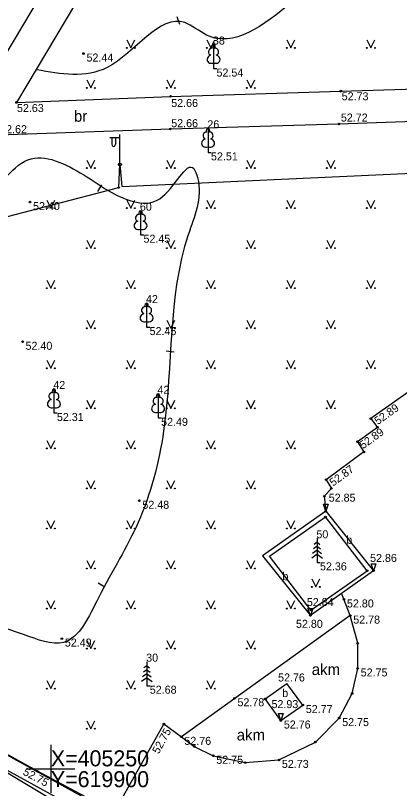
# Model space of a CAD drawing. Extents: x 619806 to 620082, y 405176 to 405386.
# Drawn here: x 619897.79 to 619921.79, y 405248.76 to 405297.03 of the extents above; entities that cross this region are included whole.
import ezdxf

# ---------------------------------------------------------------- set-up
doc = ezdxf.new("R2010")
doc.units = 0
for name, color, linetype in [('APGS_ELEM_####_####_#', 7, 'Continuous'), ('APGS_VADP_ZSPR_####_#', 7, 'Continuous'), ('BUVE_BDET_####_####_#', 7, 'Continuous'), ('BUVE_BDET_####_TKST_#', 7, 'Continuous'), ('CELI_CMAL_####_####_#', 7, 'Continuous'), ('CELI_CSEG_####_TKST_#', 7, 'Continuous'), ('CELI_SEGL_####_####_#', 7, 'Continuous'), ('GEOD_ELEM_####_####_#', 7, 'Continuous'), ('GEOD_KORD_####_TKST_#', 7, 'Continuous'), ('RELJ_AATZ_####_TKST_#', 7, 'Continuous'), ('RELJ_ELEM_####_####_#', 7, 'Continuous'), ('RELJ_HORZ_PAMT_####_#', 7, 'Continuous'), ('ROBZ_UZMR_####_####_#', 7, 'Continuous'), ('SAKK_KKAN_####_####_#', 7, 'Continuous'), ('TERT_DIAM_####_TKST_#', 7, 'Continuous'), ('TERT_ELEM_####_####_#', 7, 'Continuous')]:
    doc.layers.add(name, color=color, linetype=linetype)

msp = doc.modelspace()

# ---------------------------------------------------------------- linework, layer by layer
at = {"layer": 'APGS_ELEM_####_####_#'}
for p, q in [((619904.319, 405289.388), (619903.684, 405289.383)), ((619903.819, 405289.384), (619903.819, 405288.992)), ((619904.029, 405289.386), (619904.029, 405288.992)), ((619904.319, 405287.722), (619904.319, 405289.604))]:
    msp.add_line(p, q, dxfattribs=at)
msp.add_circle((619904.319, 405287.722), 0.09, dxfattribs=at)
msp.add_ellipse((619903.924, 405288.992), major_axis=(0, 0.151), ratio=0.695971, start_param=1.570796, end_param=4.712389, dxfattribs=at)
at = {"layer": 'APGS_VADP_ZSPR_####_#'}
msp.add_lwpolyline([(619889.151, 405287.633), (619889.486, 405287.011), (619889.44, 405286.121), (619891.102, 405284.875), (619895.261, 405283.948), (619904.24, 405286.286), (619904.319, 405287.722), (619904.441, 405286.35), (619922.582, 405287.176), (619922.83, 405287.786), (619922.954, 405287.209), (619932.902, 405287.177), (619938.46, 405286.492), (619942.211, 405287.557), (619942.781, 405287.929)], dxfattribs=at)
at = {"layer": 'BUVE_BDET_####_####_#'}
for p, q in [((619917.174, 405266.076), (619913.225, 405263.285)), ((619917.174, 405266.076), (619920.16, 405262.362)), ((619913.654, 405263.264), (619917.162, 405265.722)), ((619919.758, 405262.363), (619917.162, 405265.722)), ((619913.225, 405263.285), (619916.211, 405259.571)), ((619916.25, 405259.905), (619913.654, 405263.264)), ((619920.16, 405262.362), (619916.211, 405259.571)), ((619916.25, 405259.905), (619919.758, 405262.363)), ((619913.379, 405254.36), (619914.751, 405255.325)), ((619915.741, 405253.976), (619914.751, 405255.325)), ((619914.369, 405253.011), (619913.379, 405254.36)), ((619914.369, 405253.011), (619915.741, 405253.976))]:
    msp.add_line(p, q, dxfattribs=at)
at = {"layer": 'CELI_CMAL_####_####_#'}
msp.add_line((619918.708, 405259.562), (619908.156, 405251.991), dxfattribs=at)
for points in [[(619931.221, 405348.79), (619927.084, 405342.173), (619917.705, 405328.076), (619912.167, 405319.566), (619908.262, 405313.163), (619901.141, 405301.297), (619895.285, 405291.495)], [(619923.8, 405331.651), (619922.909, 405332.209), (619919.472, 405326.95), (619913.839, 405318.4), (619910.247, 405312.462), (619903.419, 405300.947), (619897.856, 405291.596), (619907.48, 405291.973), (619918.115, 405292.304), (619928.883, 405292.628), (619940.313, 405293.006), (619951.468, 405293.381)], [(619896.721, 405289.572), (619907.468, 405289.939), (619918, 405290.255), (619929.205, 405290.656), (619939.879, 405290.972), (619948.401, 405291.292), (619944.499, 405288.598), (619934.453, 405281.815), (619926.054, 405276.128), (619919.99, 405271.86), (619920.405, 405271.311), (619919.157, 405270.417), (619919.559, 405269.777), (619917.19, 405268.043), (619917.528, 405267.503), (619917.083, 405267.011)], [(619917.083, 405267.011), (619917.174, 405266.076)], [(619918.708, 405259.562), (619918.164, 405260.952)], [(619907.059, 405252.795), (619903.949, 405247.281), (619899.158, 405249.84), (619889.566, 405255.126)], [(619907.059, 405252.795), (619908.156, 405251.991)]]:
    msp.add_lwpolyline(points, dxfattribs=at)
at = {"layer": 'CELI_SEGL_####_####_#'}
msp.add_lwpolyline([(619908.156, 405251.991), (619908.96, 405251.391), (619910.15, 405250.809), (619912.149, 405250.384), (619914.248, 405250.551), (619916.525, 405251.669), (619918.015, 405253.162), (619918.824, 405254.696), (619919.172, 405256.263), (619919.174, 405257.833), (619918.708, 405259.562)], dxfattribs=at)
at = {"layer": 'GEOD_ELEM_####_####_#'}
for p, q in [((619900, 405251.5), (619900, 405250)), ((619898.5, 405250), (619900, 405250)), ((619900, 405250), (619900, 405248.5)), ((619900, 405250), (619901.5, 405250))]:
    msp.add_line(p, q, dxfattribs=at)
at = {"layer": 'RELJ_ELEM_####_####_#'}
for points in [[(619917.024, 405266.509), (619917.324, 405266.509), (619917.174, 405266.076)], [(619920.01, 405262.795), (619920.31, 405262.795), (619920.16, 405262.362)], [(619916.061, 405260.004), (619916.361, 405260.004), (619916.211, 405259.571)], [(619914.219, 405253.444), (619914.519, 405253.444), (619914.369, 405253.011)]]:
    msp.add_lwpolyline(points, close=True, dxfattribs=at)
for centre in [(619902.042, 405294.649), (619918.115, 405292.304), (619897.856, 405291.596), (619907.48, 405291.973), (619918, 405290.255), (619907.468, 405289.939), (619904.24, 405286.286), (619898.701, 405285.374), (619898.232, 405276.657), (619919.99, 405271.86), (619920.405, 405271.311), (619919.157, 405270.417), (619919.559, 405269.777), (619917.19, 405268.043), (619917.528, 405267.503), (619917.083, 405267.011), (619905.532, 405266.73), (619917.174, 405266.076), (619917.162, 405265.722), (619919.758, 405262.363), (619920.16, 405262.362), (619918.314, 405260.569), (619916.25, 405259.905), (619916.211, 405259.571), (619918.708, 405259.562), (619900.688, 405258.126), (619919.174, 405257.833), (619919.172, 405256.263), (619911.473, 405254.4), (619913.379, 405254.36), (619913.414, 405254.36), (619918.824, 405254.696), (619915.741, 405253.976), (619914.369, 405253.011), (619918.015, 405253.162), (619907.059, 405252.795), (619908.156, 405251.991), (619916.525, 405251.669), (619908.96, 405251.391), (619910.15, 405250.809), (619914.248, 405250.551), (619912.149, 405250.384), (619899.158, 405249.84)]:
    msp.add_circle(centre, 0.05, dxfattribs=at)
at = {"layer": 'RELJ_HORZ_PAMT_####_#'}
for p, q in [((619907.874, 405296.963), (619908.041, 405296.492)), ((619902.928, 405286.035), (619903.188, 405286.462)), ((619907.198, 405276.089), (619907.695, 405276.03)), ((619902.951, 405261.609), (619903.381, 405261.354))]:
    msp.add_line(p, q, dxfattribs=at)
for points in [[(619907.956, 405308.464), (619910.402, 405307.562), (619913.86, 405304.951), (619915.602, 405304.09), (619915.602, 405305.597), (619912.968, 405313.592), (619912.89, 405315.511), (619914.687, 405318.349), (619915.7, 405320.324), (619916.9, 405321.328), (619919.524, 405322.347), (619920.794, 405321.7), (619918.865, 405319.529), (619916.618, 405315.954), (619917.647, 405309.917), (619920.445, 405301.831), (619920.93, 405298.602), (619919.742, 405298.823), (619918.41, 405299.521), (619915.057, 405297.864), (619909.729, 405295.803), (619908.377, 405296.58), (619903.524, 405293.78), (619899.119, 405293.642)], [(619887.855, 405269.148), (619889.12, 405269.976), (619890.345, 405272.168), (619891.345, 405274.665), (619892.785, 405275.65), (619894.673, 405276.824), (619895.637, 405278.889), (619895.637, 405282.116), (619896.178, 405285.879), (619897.087, 405286.842), (619898.566, 405288.02), (619902.05, 405287.072), (619905.151, 405285.41), (619906.813, 405285.589), (619908.935, 405287.464), (619909.163, 405286.902), (619908.582, 405283.331), (619907.046, 405271.1), (619905.455, 405265.372), (619902.979, 405260.677), (619900.798, 405257.889), (619898.289, 405258.38), (619891.711, 405260.242), (619887.92, 405262.299), (619887.202, 405264.358), (619886.645, 405266.658)]]:
    msp.add_spline(points, degree=3, dxfattribs=at)
at = {"layer": 'ROBZ_UZMR_####_####_#'}
msp.add_line((619903.919, 405247.191), (619882.718, 405258.864), dxfattribs=at)
at = {"layer": 'SAKK_KKAN_####_####_#'}
for points in [[(619816.151, 405294.73), (619816.825, 405294), (619832.922, 405285.576), (619895.115, 405251.073), (619918.714, 405238.138)], [(619895.171, 405251.006), (619903.851, 405245.802), (619901.291, 405240.588)]]:
    msp.add_lwpolyline(points, dxfattribs=at)
at = {"layer": 'TERT_ELEM_####_####_#'}
for p, q in [((619904.75, 405295.5), (619905, 405295)), ((619905, 405295), (619905.25, 405295.5)), ((619909.75, 405295.5), (619910, 405295)), ((619910, 405295), (619910.25, 405295.5)), ((619914.75, 405295.5), (619915, 405295)), ((619915, 405295), (619915.25, 405295.5)), ((619919.75, 405295.5), (619920, 405295)), ((619920, 405295), (619920.25, 405295.5)), ((619910.164, 405294.058), (619910.164, 405293.711)), ((619910.164, 405293.711), (619910.364, 405293.711)), ((619902.25, 405293), (619902.5, 405292.5)), ((619902.5, 405292.5), (619902.75, 405293)), ((619907.25, 405293), (619907.5, 405292.5)), ((619907.5, 405292.5), (619907.75, 405293)), ((619912.25, 405293), (619912.5, 405292.5)), ((619912.5, 405292.5), (619912.75, 405293)), ((619909.818, 405288.827), (619909.818, 405288.48)), ((619909.818, 405288.48), (619910.018, 405288.48)), ((619902.25, 405288), (619902.5, 405287.5)), ((619902.5, 405287.5), (619902.75, 405288)), ((619907.25, 405288), (619907.5, 405287.5)), ((619907.5, 405287.5), (619907.75, 405288)), ((619912.25, 405288), (619912.5, 405287.5)), ((619912.5, 405287.5), (619912.75, 405288)), ((619917.25, 405288), (619917.5, 405287.5)), ((619917.5, 405287.5), (619917.75, 405288)), ((619899.75, 405285.5), (619900, 405285)), ((619900, 405285), (619900.25, 405285.5)), ((619904.75, 405285.5), (619905, 405285)), ((619905, 405285), (619905.25, 405285.5)), ((619909.75, 405285.5), (619910, 405285)), ((619910, 405285), (619910.25, 405285.5)), ((619914.75, 405285.5), (619915, 405285)), ((619915, 405285), (619915.25, 405285.5)), ((619919.75, 405285.5), (619920, 405285)), ((619920, 405285), (619920.25, 405285.5)), ((619905.601, 405283.686), (619905.601, 405283.339)), ((619902.25, 405283), (619902.5, 405282.5)), ((619902.5, 405282.5), (619902.75, 405283)), ((619905.601, 405283.339), (619905.801, 405283.339)), ((619907.25, 405283), (619907.5, 405282.5)), ((619907.5, 405282.5), (619907.75, 405283)), ((619912.25, 405283), (619912.5, 405282.5)), ((619912.5, 405282.5), (619912.75, 405283)), ((619917.25, 405283), (619917.5, 405282.5)), ((619917.5, 405282.5), (619917.75, 405283)), ((619899.75, 405280.5), (619900, 405280)), ((619900, 405280), (619900.25, 405280.5)), ((619904.75, 405280.5), (619905, 405280)), ((619905, 405280), (619905.25, 405280.5)), ((619909.75, 405280.5), (619910, 405280)), ((619910, 405280), (619910.25, 405280.5)), ((619914.75, 405280.5), (619915, 405280)), ((619915, 405280), (619915.25, 405280.5)), ((619919.75, 405280.5), (619920, 405280)), ((619920, 405280), (619920.25, 405280.5)), ((619902.25, 405278), (619902.5, 405277.5)), ((619902.5, 405277.5), (619902.75, 405278)), ((619905.983, 405277.92), (619905.983, 405277.573)), ((619905.983, 405277.573), (619906.183, 405277.573)), ((619907.25, 405278), (619907.5, 405277.5)), ((619907.5, 405277.5), (619907.75, 405278)), ((619912.25, 405278), (619912.5, 405277.5)), ((619912.5, 405277.5), (619912.75, 405278)), ((619917.25, 405278), (619917.5, 405277.5)), ((619917.5, 405277.5), (619917.75, 405278)), ((619899.75, 405275.5), (619900, 405275)), ((619900, 405275), (619900.25, 405275.5)), ((619904.75, 405275.5), (619905, 405275)), ((619905, 405275), (619905.25, 405275.5)), ((619909.75, 405275.5), (619910, 405275)), ((619910, 405275), (619910.25, 405275.5)), ((619914.75, 405275.5), (619915, 405275)), ((619915, 405275), (619915.25, 405275.5)), ((619919.75, 405275.5), (619920, 405275)), ((619920, 405275), (619920.25, 405275.5)), ((619902.25, 405273), (619902.5, 405272.5)), ((619902.5, 405272.5), (619902.75, 405273)), ((619907.25, 405273), (619907.5, 405272.5)), ((619907.5, 405272.5), (619907.75, 405273)), ((619912.25, 405273), (619912.5, 405272.5)), ((619912.5, 405272.5), (619912.75, 405273)), ((619917.25, 405273), (619917.5, 405272.5)), ((619917.5, 405272.5), (619917.75, 405273)), ((619900.191, 405272.556), (619900.191, 405272.209)), ((619906.702, 405272.255), (619906.702, 405271.908)), ((619900.191, 405272.209), (619900.391, 405272.209)), ((619906.702, 405271.908), (619906.902, 405271.908)), ((619899.75, 405270.5), (619900, 405270)), ((619900, 405270), (619900.25, 405270.5)), ((619904.75, 405270.5), (619905, 405270)), ((619905, 405270), (619905.25, 405270.5)), ((619909.75, 405270.5), (619910, 405270)), ((619910, 405270), (619910.25, 405270.5)), ((619914.75, 405270.5), (619915, 405270)), ((619915, 405270), (619915.25, 405270.5)), ((619902.25, 405268), (619902.5, 405267.5)), ((619902.5, 405267.5), (619902.75, 405268)), ((619907.25, 405268), (619907.5, 405267.5)), ((619907.5, 405267.5), (619907.75, 405268)), ((619912.25, 405268), (619912.5, 405267.5)), ((619912.5, 405267.5), (619912.75, 405268)), ((619899.75, 405265.5), (619900, 405265)), ((619900, 405265), (619900.25, 405265.5)), ((619904.75, 405265.5), (619905, 405265)), ((619905, 405265), (619905.25, 405265.5)), ((619909.75, 405265.5), (619910, 405265)), ((619910, 405265), (619910.25, 405265.5)), ((619914.75, 405265.5), (619915, 405265)), ((619915, 405265), (619915.25, 405265.5)), ((619916.629, 405264.136), (619916.453, 405264.008)), ((619916.629, 405264.386), (619916.629, 405262.886)), ((619916.629, 405264.136), (619916.803, 405264.008)), ((619916.629, 405263.636), (619916.351, 405263.432)), ((619916.629, 405263.886), (619916.413, 405263.728)), ((619916.629, 405263.886), (619916.845, 405263.728)), ((619916.629, 405263.636), (619916.907, 405263.432)), ((619916.629, 405263.386), (619916.297, 405263.142)), ((619916.629, 405263.386), (619916.963, 405263.142)), ((619902.25, 405263), (619902.5, 405262.5)), ((619902.5, 405262.5), (619902.75, 405263)), ((619907.25, 405263), (619907.5, 405262.5)), ((619907.5, 405262.5), (619907.75, 405263)), ((619912.25, 405263), (619912.5, 405262.5)), ((619912.5, 405262.5), (619912.75, 405263)), ((619916.629, 405262.886), (619916.829, 405262.886)), ((619916.298, 405261.851), (619916.548, 405261.351)), ((619916.548, 405261.351), (619916.798, 405261.851)), ((619899.75, 405260.5), (619900, 405260)), ((619900, 405260), (619900.25, 405260.5)), ((619904.75, 405260.5), (619905, 405260)), ((619905, 405260), (619905.25, 405260.5)), ((619909.75, 405260.5), (619910, 405260)), ((619910, 405260), (619910.25, 405260.5)), ((619914.75, 405260.5), (619915, 405260)), ((619915, 405260), (619915.25, 405260.5)), ((619902.25, 405258), (619902.5, 405257.5)), ((619902.5, 405257.5), (619902.75, 405258)), ((619907.25, 405258), (619907.5, 405257.5)), ((619907.5, 405257.5), (619907.75, 405258)), ((619912.25, 405258), (619912.5, 405257.5)), ((619912.5, 405257.5), (619912.75, 405258)), ((619905.994, 405256.434), (619905.818, 405256.306)), ((619905.994, 405256.684), (619905.994, 405255.184)), ((619905.994, 405256.434), (619906.168, 405256.306)), ((619905.994, 405255.934), (619905.716, 405255.73)), ((619905.994, 405256.184), (619905.778, 405256.026)), ((619905.994, 405256.184), (619906.21, 405256.026)), ((619905.994, 405255.934), (619906.272, 405255.73)), ((619899.75, 405255.5), (619900, 405255)), ((619900, 405255), (619900.25, 405255.5)), ((619904.75, 405255.5), (619905, 405255)), ((619905, 405255), (619905.25, 405255.5)), ((619905.994, 405255.684), (619905.662, 405255.44)), ((619905.994, 405255.684), (619906.328, 405255.44)), ((619909.75, 405255.5), (619910, 405255)), ((619910, 405255), (619910.25, 405255.5)), ((619905.994, 405255.184), (619906.194, 405255.184)), ((619902.25, 405253), (619902.5, 405252.5)), ((619902.5, 405252.5), (619902.75, 405253))]:
    msp.add_line(p, q, dxfattribs=at)
for points in [[(619910.164, 405295.211), (619910.164, 405294.058)], [(619910.254, 405294.979), (619910.253, 405294.98)], [(619909.818, 405289.98), (619909.818, 405288.827)], [(619909.908, 405289.748), (619909.907, 405289.749)], [(619905.601, 405284.839), (619905.601, 405283.686)], [(619905.691, 405284.607), (619905.69, 405284.608)], [(619905.983, 405279.073), (619905.983, 405277.92)], [(619906.073, 405278.841), (619906.072, 405278.842)], [(619900.191, 405273.709), (619900.191, 405272.556)], [(619900.281, 405273.477), (619900.28, 405273.478)], [(619906.702, 405273.408), (619906.702, 405272.255)], [(619906.792, 405273.176), (619906.791, 405273.177)]]:
    msp.add_lwpolyline(points, dxfattribs=at)
for centre, radius in [((619904.75, 405295), 0.028), ((619905.25, 405295), 0.0263), ((619909.75, 405295), 0.028), ((619910.25, 405295), 0.0263), ((619914.75, 405295), 0.028), ((619915.25, 405295), 0.0263), ((619919.75, 405295), 0.028), ((619920.25, 405295), 0.0263), ((619902.25, 405292.5), 0.028), ((619902.75, 405292.5), 0.0263), ((619907.25, 405292.5), 0.028), ((619907.75, 405292.5), 0.0263), ((619912.25, 405292.5), 0.028), ((619912.75, 405292.5), 0.0263), ((619902.25, 405287.5), 0.028), ((619902.75, 405287.5), 0.0263), ((619907.25, 405287.5), 0.028), ((619907.75, 405287.5), 0.0263), ((619912.25, 405287.5), 0.028), ((619912.75, 405287.5), 0.0263), ((619917.25, 405287.5), 0.028), ((619917.75, 405287.5), 0.0263), ((619899.75, 405285), 0.028), ((619900.25, 405285), 0.0263), ((619904.75, 405285), 0.028), ((619905.25, 405285), 0.0263), ((619909.75, 405285), 0.028), ((619910.25, 405285), 0.0263), ((619914.75, 405285), 0.028), ((619915.25, 405285), 0.0263), ((619919.75, 405285), 0.028), ((619920.25, 405285), 0.0263), ((619902.25, 405282.5), 0.028), ((619902.75, 405282.5), 0.0263), ((619907.25, 405282.5), 0.028), ((619907.75, 405282.5), 0.0263), ((619912.25, 405282.5), 0.028), ((619912.75, 405282.5), 0.0263), ((619917.25, 405282.5), 0.028), ((619917.75, 405282.5), 0.0263), ((619899.75, 405280), 0.028), ((619900.25, 405280), 0.0263), ((619904.75, 405280), 0.028), ((619905.25, 405280), 0.0263), ((619909.75, 405280), 0.028), ((619910.25, 405280), 0.0263), ((619914.75, 405280), 0.028), ((619915.25, 405280), 0.0263), ((619919.75, 405280), 0.028), ((619920.25, 405280), 0.0263), ((619902.25, 405277.5), 0.028), ((619902.75, 405277.5), 0.0263), ((619907.25, 405277.5), 0.028), ((619907.75, 405277.5), 0.0263), ((619912.25, 405277.5), 0.028), ((619912.75, 405277.5), 0.0263), ((619917.25, 405277.5), 0.028), ((619917.75, 405277.5), 0.0263), ((619899.75, 405275), 0.028), ((619900.25, 405275), 0.0263), ((619904.75, 405275), 0.028), ((619905.25, 405275), 0.0263), ((619909.75, 405275), 0.028), ((619910.25, 405275), 0.0263), ((619914.75, 405275), 0.028), ((619915.25, 405275), 0.0263), ((619919.75, 405275), 0.028), ((619920.25, 405275), 0.0263), ((619902.25, 405272.5), 0.028), ((619902.75, 405272.5), 0.0263), ((619907.25, 405272.5), 0.028), ((619907.75, 405272.5), 0.0263), ((619912.25, 405272.5), 0.028), ((619912.75, 405272.5), 0.0263), ((619917.25, 405272.5), 0.028), ((619917.75, 405272.5), 0.0263), ((619899.75, 405270), 0.028), ((619900.25, 405270), 0.0263), ((619904.75, 405270), 0.028), ((619905.25, 405270), 0.0263), ((619909.75, 405270), 0.028), ((619910.25, 405270), 0.0263), ((619914.75, 405270), 0.028), ((619915.25, 405270), 0.0263), ((619902.25, 405267.5), 0.028), ((619902.75, 405267.5), 0.0263), ((619907.25, 405267.5), 0.028), ((619907.75, 405267.5), 0.0263), ((619912.25, 405267.5), 0.028), ((619912.75, 405267.5), 0.0263), ((619899.75, 405265), 0.028), ((619900.25, 405265), 0.0263), ((619904.75, 405265), 0.028), ((619905.25, 405265), 0.0263), ((619909.75, 405265), 0.028), ((619910.25, 405265), 0.0263), ((619914.75, 405265), 0.028), ((619915.25, 405265), 0.0263), ((619902.25, 405262.5), 0.028), ((619902.75, 405262.5), 0.0263), ((619907.25, 405262.5), 0.028), ((619907.75, 405262.5), 0.0263), ((619912.25, 405262.5), 0.028), ((619912.75, 405262.5), 0.0263), ((619916.298, 405261.35), 0.028), ((619916.798, 405261.35), 0.0263), ((619899.75, 405260), 0.028), ((619900.25, 405260), 0.0263), ((619904.75, 405260), 0.028), ((619905.25, 405260), 0.0263), ((619909.75, 405260), 0.028), ((619910.25, 405260), 0.0263), ((619914.75, 405260), 0.028), ((619915.25, 405260), 0.0263), ((619902.25, 405257.5), 0.028), ((619902.75, 405257.5), 0.0263), ((619907.25, 405257.5), 0.028), ((619907.75, 405257.5), 0.0263), ((619912.25, 405257.5), 0.028), ((619912.75, 405257.5), 0.0263), ((619899.75, 405255), 0.028), ((619900.25, 405255), 0.0263), ((619904.75, 405255), 0.028), ((619905.25, 405255), 0.0263), ((619909.75, 405255), 0.028), ((619910.25, 405255), 0.0263), ((619902.25, 405252.5), 0.028), ((619902.75, 405252.5), 0.0263)]:
    msp.add_circle(centre, radius, dxfattribs=at)
for centre, major_axis, ratio, start_param, end_param in [((619910.036, 405294.766), (-0.039, -0.212), 0.861323, 3.141593, 6.283185), ((619910.164, 405295.061), (0, -0.15), 0.707107, 3.14537, 5.287485), ((619910.164, 405295.061), (0, -0.15), 0.707107, 0.995701, 3.137816), ((619910.292, 405294.766), (0.039, -0.212), 0.861323, 0, 3.141593), ((619910.074, 405294.304), (0.307, 0.095), 0.814445, 1.570796, 4.752015), ((619910.254, 405294.304), (-0.307, 0.095), 0.814445, 1.531171, 4.712389), ((619909.69, 405289.535), (-0.039, -0.212), 0.861323, 3.141593, 6.283185), ((619909.818, 405289.83), (0, -0.15), 0.707107, 3.14537, 5.287485), ((619909.818, 405289.83), (0, -0.15), 0.707107, 0.995701, 3.137816), ((619909.946, 405289.535), (0.039, -0.212), 0.861323, 0, 3.141593), ((619909.728, 405289.073), (0.307, 0.095), 0.814445, 1.570796, 4.752015), ((619909.908, 405289.073), (-0.307, 0.095), 0.814445, 1.531171, 4.712389), ((619905.601, 405284.689), (0, -0.15), 0.707107, 3.14537, 5.287485), ((619905.601, 405284.689), (0, -0.15), 0.707107, 0.995701, 3.137816), ((619905.473, 405284.394), (-0.039, -0.212), 0.861323, 3.141593, 6.283185), ((619905.729, 405284.394), (0.039, -0.212), 0.861323, 0, 3.141593), ((619905.511, 405283.932), (0.307, 0.095), 0.814445, 1.570796, 4.752015), ((619905.691, 405283.932), (-0.307, 0.095), 0.814445, 1.531171, 4.712389), ((619905.983, 405278.923), (0, -0.15), 0.707107, 3.14537, 5.287485), ((619905.983, 405278.923), (0, -0.15), 0.707107, 0.995701, 3.137816), ((619905.855, 405278.628), (-0.039, -0.212), 0.861323, 3.141593, 6.283185), ((619906.111, 405278.628), (0.039, -0.212), 0.861323, 0, 3.141593), ((619905.893, 405278.166), (0.307, 0.095), 0.814445, 1.570796, 4.752015), ((619906.073, 405278.166), (-0.307, 0.095), 0.814445, 1.531171, 4.712389), ((619900.191, 405273.559), (0, -0.15), 0.707107, 3.14537, 5.287485), ((619900.191, 405273.559), (0, -0.15), 0.707107, 0.995701, 3.137816), ((619900.063, 405273.264), (-0.039, -0.212), 0.861323, 3.141593, 6.283185), ((619900.319, 405273.264), (0.039, -0.212), 0.861323, 0, 3.141593), ((619906.702, 405273.258), (0, -0.15), 0.707107, 3.14537, 5.287485), ((619906.702, 405273.258), (0, -0.15), 0.707107, 0.995701, 3.137816), ((619900.101, 405272.802), (0.307, 0.095), 0.814445, 1.570796, 4.752015), ((619900.281, 405272.802), (-0.307, 0.095), 0.814445, 1.531171, 4.712389), ((619906.612, 405272.501), (0.307, 0.095), 0.814445, 1.570796, 4.752015), ((619906.574, 405272.963), (-0.039, -0.212), 0.861323, 3.141593, 6.283185), ((619906.792, 405272.501), (-0.307, 0.095), 0.814445, 1.531171, 4.712389), ((619906.83, 405272.963), (0.039, -0.212), 0.861323, 0, 3.141593)]:
    msp.add_ellipse(centre, major_axis=major_axis, ratio=ratio, start_param=start_param, end_param=end_param, dxfattribs=at)

# ---------------------------------------------------------------- texts
at = {"layer": 'BUVE_BDET_####_TKST_#'}
for p in [(619918.46, 405264.043), (619914.468, 405261.771), (619914.456, 405254.48)]:
    msp.add_text('b', height=0.5, dxfattribs=at).set_placement(p)
at = {"layer": 'CELI_CSEG_####_TKST_#'}
for s, p in [('br', (619901.44, 405290.391)), ('akm', (619916.301, 405255.851)), ('akm', (619911.612, 405251.765))]:
    msp.add_text(s, height=0.7, dxfattribs=at).set_placement(p)
at = {"layer": 'GEOD_KORD_####_TKST_#'}
for s, p in [('X=405250', (619900, 405250.15)), ('Y=619900', (619900, 405248.85))]:
    msp.add_text(s, height=1, dxfattribs=at).set_placement(p)
at = {"layer": 'RELJ_AATZ_####_TKST_#'}
for s, p in [(' 52.44', (619902.042, 405294.149)), (' 52.54', (619910.164, 405293.211)), (' 52.73', (619917.985, 405291.732)), (' 52.66', (619907.333, 405291.311)), (' 52.63', (619897.696, 405290.999)), (' 52.72', (619917.933, 405290.404)), (' 52.62', (619896.647, 405289.676)), (' 52.66', (619907.335, 405290.051)), (' 52.51', (619909.818, 405287.98)), (' 52.40', (619898.701, 405284.874)), (' 52.45', (619905.601, 405282.839)), (' 52.45', (619905.983, 405277.073)), (' 52.40', (619898.232, 405276.157)), (' 52.31', (619900.191, 405271.709)), (' 52.49', (619906.702, 405271.408)), (' 52.85', (619917.174, 405266.673)), (' 52.48', (619905.532, 405266.23)), (' 52.86', (619919.758, 405262.91)), (' 52.36', (619916.629, 405262.386)), (' 52.84', (619915.808, 405260.157)), (' 52.80', (619918.314, 405260.069)), (' 52.80', (619915.129, 405258.798)), (' 52.78', (619918.708, 405259.062)), (' 52.49', (619900.688, 405257.626)), (' 52.76', (619914.01, 405255.447)), (' 52.75', (619919.172, 405255.763)), (' 52.68', (619905.994, 405254.684)), (' 52.78', (619911.473, 405253.9)), (' 52.93', (619913.599, 405253.785)), (' 52.77', (619915.741, 405253.476)), (' 52.76', (619914.369, 405252.511)), (' 52.75', (619918.015, 405252.662)), (' 52.76', (619908.156, 405251.491)), (' 52.75', (619910.15, 405250.309)), (' 52.73', (619914.248, 405250.051))]:
    msp.add_text(s, height=0.5, dxfattribs=at).set_placement(p)
for s, rotation, p in [(' 52.89', 35.1389, (619920.278, 405271.342)), (' 52.89', 35.6158, (619919.35, 405269.828)), (' 52.87', 36.2024, (619917.485, 405267.496)), (' 52.75', 61.2611, (619906.647, 405250.723)), (' 52.75', 331.8921, (619898.048, 405249.738))]:
    msp.add_text(s, height=0.5, rotation=rotation, dxfattribs=at).set_placement(p)
at = {"layer": 'TERT_DIAM_####_TKST_#'}
for s, p in [(' 38', (619909.939, 405295.211)), (' 26', (619909.593, 405289.98)), (' 60', (619905.376, 405284.839)), (' 42', (619905.758, 405279.073)), (' 42', (619899.966, 405273.709)), (' 42', (619906.477, 405273.408)), (' 50', (619916.404, 405264.386)), (' 30', (619905.769, 405256.684))]:
    msp.add_text(s, height=0.5, dxfattribs=at).set_placement(p)

doc.saveas('drawing.dxf')
